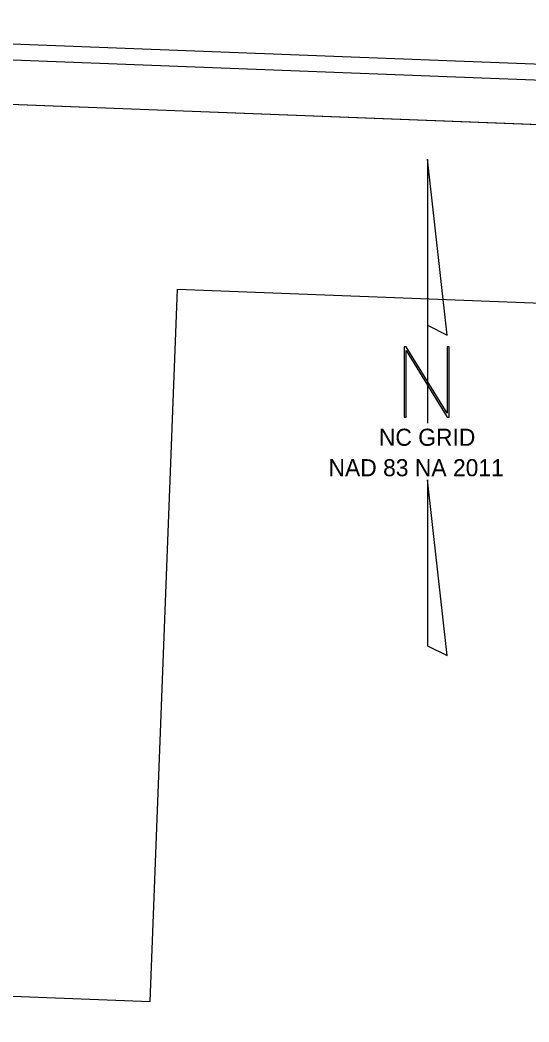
# Model space of a CAD drawing. Extents: x 2097431 to 2097897, y 685861 to 686794.
# Drawn here: x 2097528.3 to 2097585.5, y 686582.8 to 686695.3 of the extents above; entities that cross this region are included whole.
import ezdxf

# ---------------------------------------------------------------- set-up
doc = ezdxf.new("R2010")
doc.units = 0
for name, color, linetype in [('Default', 7, 'Continuous'), ('Scratch_Level_5', 7, 'Continuous'), ('Sheet Layout Plan Border', 7, 'Continuous'), ('Sheet Plan And Profile CELL', 7, 'Continuous'), ('Sheet Plot Border Inside CELL', 7, 'Continuous'), ('Sheet Plot Border Outside CELL', 7, 'Continuous'), ('Sheet Profile CELL', 7, 'Continuous')]:
    doc.layers.add(name, color=color, linetype=linetype)

msp = doc.modelspace()

# ---------------------------------------------------------------- linework, layer by layer
at = {"layer": 'Default'}
msp.add_line((2097574.1, 686651.81), (2097574.1, 686651.81), dxfattribs=at)
for points in [[(2097574.05, 686679.74), (2097574.05, 686661.07), (2097576.25, 686659.97)], [(2097571.42, 686650.76), (2097571.64, 686650.76), (2097571.64, 686658.23), (2097576.25, 686650.76), (2097576.47, 686650.76), (2097576.47, 686658.66), (2097576.25, 686658.66), (2097576.25, 686651.2), (2097571.64, 686658.66), (2097571.42, 686658.66)], [(2097574.05, 686625.07), (2097576.25, 686623.98), (2097574.05, 686643.73)]]:
    msp.add_lwpolyline(points, close=True, dxfattribs=at)
msp.add_lwpolyline([(2097574.05, 686661.07), (2097574.05, 686650.1)], dxfattribs=at)
at = {"layer": 'Scratch_Level_5'}
msp.add_lwpolyline([(2097443.76, 686088.61), (2097699.44, 686078.8), (2097722.44, 686678.36), (2097503.65, 686686.75), (2097500.59, 686606.79), (2097463.68, 686608.21)], close=True, dxfattribs=at)
at = {"layer": 'Sheet Layout Plan Border'}
msp.add_lwpolyline([(2097644.38, 686100.93), (2097464.51, 686107.83), (2097482.9, 686587.46), (2097542.88, 686585.16), (2097545.95, 686665.12), (2097665.84, 686660.52)], close=True, dxfattribs=at)
at = {"layer": 'Sheet Plan And Profile CELL'}
msp.add_lwpolyline([(2097466.75, 686688.17), (2097443.76, 686088.61), (2097863.45, 686072.51), (2097886.44, 686672.07)], close=True, dxfattribs=at)
at = {"layer": 'Sheet Plot Border Inside CELL'}
msp.add_lwpolyline([(2097862.11, 686010.92), (2097887.65, 686677.03), (2097465.92, 686693.2), (2097440.38, 686027.09)], close=True, dxfattribs=at)
at = {"layer": 'Sheet Plot Border Outside CELL'}
msp.add_lwpolyline([(2097870.88, 686005.38), (2097896.7, 686678.48), (2097457.02, 686695.35), (2097431.2, 686022.24)], close=True, dxfattribs=at)
at = {"layer": 'Sheet Profile CELL'}
msp.add_lwpolyline([(2097466.75, 686688.17), (2097443.76, 686088.61), (2097863.45, 686072.51), (2097886.44, 686672.07)], close=True, dxfattribs=at)

# ---------------------------------------------------------------- texts
at = {"layer": 'Default'}
for s, p in [('NC GRID', (2097568.59, 686647.54)), ('NAD 83 NA 2011', (2097562.93, 686644.12))]:
    msp.add_text(s, height=1.92, dxfattribs=at).set_placement(p)

doc.saveas('drawing.dxf')
